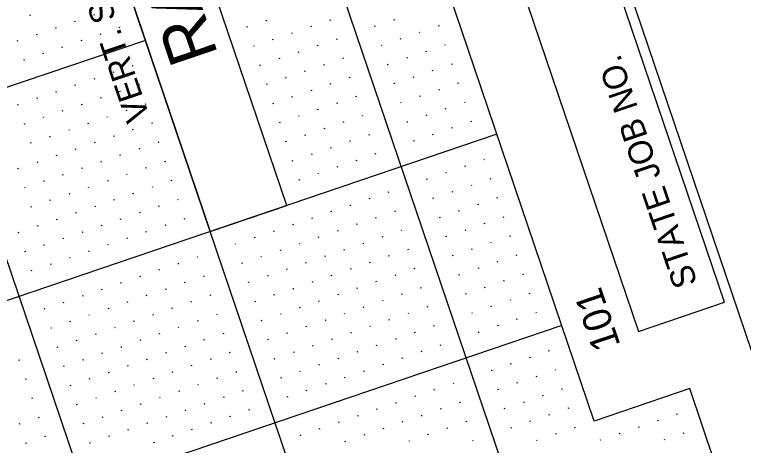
# Model space of a CAD drawing. Extents: x 2150318 to 2152065, y 143281 to 145371.
# Drawn here: x 2151290.7 to 2151471.2, y 145032.3 to 145139 of the extents above; entities that cross this region are included whole.
import ezdxf

# ---------------------------------------------------------------- set-up
doc = ezdxf.new("R2010")
doc.units = 0
for name, color, linetype in [('PR_Align_Ramp_J_Sta', 7, 'Continuous'), ('SHT_Plan_Profile_Sheet_Sta_Txt', 7, 'Continuous'), ('SHT_Plan_Profile_Sheet_Txt', 7, 'Continuous'), ('SHT_Profile_Grid_Major', 7, 'Continuous'), ('SHT_Profile_Grid_Minor', 7, 'Continuous'), ('SHT_Scale', 7, 'Continuous'), ('SHT_Sheet_Border', 7, 'Continuous')]:
    doc.layers.add(name, color=color, linetype=linetype)

msp = doc.modelspace()

# ---------------------------------------------------------------- linework, layer by layer
at = {"layer": 'SHT_Profile_Grid_Major'}
for p, q in [((2151832.26, 143787.41), (2151326.27, 145278.92)), ((2151784.91, 143771.34), (2151278.93, 145262.85)), ((2151737.57, 143755.28), (2151231.58, 145246.79)), ((2151323.1, 145132.64), (2150944.3, 145004.14)), ((2151410.19, 145109.39), (2150960.37, 144956.79)), ((2151426.25, 145062.04), (2150976.43, 144909.44))]:
    msp.add_line(p, q, dxfattribs=at)
at = {"layer": 'SHT_Profile_Grid_Minor'}
for p, q in [((2151294.65, 145138.7), (2151294.56, 145138.93)), ((2151305.72, 145137.17), (2151305.64, 145137.41)), ((2151310.46, 145138.78), (2151310.38, 145139.02)), ((2151353.15, 145137.43), (2151353.07, 145137.66)), ((2151368.97, 145137.51), (2151368.89, 145137.75)), ((2151384.78, 145137.59), (2151384.7, 145137.83)), ((2151300.99, 145135.57), (2151300.91, 145135.81)), ((2151316.8, 145135.65), (2151316.72, 145135.89)), ((2151348.42, 145135.82), (2151348.34, 145136.06)), ((2151364.23, 145135.9), (2151364.15, 145136.14)), ((2151380.04, 145135.99), (2151379.96, 145136.23)), ((2151395.85, 145136.07), (2151395.77, 145136.31)), ((2151296.25, 145133.96), (2151296.17, 145134.2)), ((2151312.06, 145134.05), (2151311.98, 145134.28)), ((2151359.5, 145134.3), (2151359.42, 145134.53)), ((2151391.12, 145134.47), (2151391.04, 145134.7)), ((2151291.52, 145132.36), (2151291.44, 145132.59)), ((2151307.33, 145132.44), (2151307.25, 145132.68)), ((2151354.76, 145132.69), (2151354.68, 145132.93)), ((2151370.57, 145132.78), (2151370.49, 145133.01)), ((2151386.38, 145132.86), (2151386.3, 145133.1)), ((2151302.59, 145130.83), (2151302.51, 145131.07)), ((2151350.03, 145131.09), (2151349.95, 145131.32)), ((2151365.84, 145131.17), (2151365.76, 145131.41)), ((2151381.65, 145131.25), (2151381.57, 145131.49)), ((2151397.46, 145131.34), (2151397.38, 145131.57)), ((2151297.86, 145129.23), (2151297.78, 145129.46)), ((2151361.1, 145129.56), (2151361.02, 145129.8)), ((2151392.72, 145129.73), (2151392.64, 145129.97)), ((2151293.12, 145127.62), (2151293.04, 145127.86)), ((2151351.63, 145126.35), (2151351.55, 145126.59)), ((2151356.37, 145127.96), (2151356.29, 145128.19)), ((2151367.44, 145126.43), (2151367.36, 145126.67)), ((2151372.18, 145128.04), (2151372.1, 145128.28)), ((2151383.25, 145126.52), (2151383.17, 145126.76)), ((2151387.99, 145128.12), (2151387.91, 145128.36)), ((2151399.07, 145126.6), (2151398.99, 145126.84)), ((2151315.28, 145124.58), (2151315.19, 145124.81)), ((2151320.01, 145126.18), (2151319.93, 145126.42)), ((2151362.71, 145124.83), (2151362.63, 145125.06)), ((2151394.33, 145125), (2151394.25, 145125.23)), ((2151310.54, 145122.97), (2151310.46, 145123.21)), ((2151357.97, 145123.22), (2151357.89, 145123.46)), ((2151373.78, 145123.31), (2151373.7, 145123.54)), ((2151389.6, 145123.39), (2151389.52, 145123.63)), ((2151305.81, 145121.36), (2151305.73, 145121.6)), ((2151321.62, 145121.45), (2151321.54, 145121.68)), ((2151353.24, 145121.62), (2151353.16, 145121.85)), ((2151369.05, 145121.7), (2151368.97, 145121.94)), ((2151384.86, 145121.78), (2151384.78, 145122.02)), ((2151400.67, 145121.87), (2151400.59, 145122.1)), ((2151301.07, 145119.76), (2151300.99, 145119.99)), ((2151316.88, 145119.84), (2151316.8, 145120.08)), ((2151364.32, 145120.09), (2151364.23, 145120.33)), ((2151395.94, 145120.26), (2151395.86, 145120.5)), ((2151296.34, 145118.15), (2151296.26, 145118.39)), ((2151312.15, 145118.23), (2151312.07, 145118.47)), ((2151359.58, 145118.49), (2151359.5, 145118.72)), ((2151375.39, 145118.57), (2151375.31, 145118.81)), ((2151391.2, 145118.65), (2151391.12, 145118.89)), ((2151291.6, 145116.54), (2151291.52, 145116.78)), ((2151307.41, 145116.63), (2151307.33, 145116.87)), ((2151323.22, 145116.71), (2151323.14, 145116.95)), ((2151354.85, 145116.88), (2151354.76, 145117.12)), ((2151370.66, 145116.96), (2151370.58, 145117.2)), ((2151386.47, 145117.05), (2151386.39, 145117.29)), ((2151397.54, 145115.53), (2151397.46, 145115.76)), ((2151402.28, 145117.13), (2151402.2, 145117.37)), ((2151302.68, 145115.02), (2151302.6, 145115.26)), ((2151318.49, 145115.11), (2151318.41, 145115.34)), ((2151361.19, 145113.75), (2151361.11, 145113.99)), ((2151365.92, 145115.36), (2151365.84, 145115.59)), ((2151377, 145113.84), (2151376.92, 145114.07)), ((2151392.81, 145113.92), (2151392.73, 145114.16)), ((2151297.94, 145113.42), (2151297.86, 145113.65)), ((2151309.02, 145111.89), (2151308.94, 145112.13)), ((2151313.75, 145113.5), (2151313.67, 145113.74)), ((2151324.83, 145111.98), (2151324.75, 145112.21)), ((2151356.45, 145112.15), (2151356.37, 145112.38)), ((2151372.26, 145112.23), (2151372.18, 145112.47)), ((2151388.07, 145112.31), (2151387.99, 145112.55)), ((2151403.89, 145112.4), (2151403.8, 145112.63)), ((2151293.21, 145111.81), (2151293.13, 145112.05)), ((2151304.28, 145110.29), (2151304.2, 145110.52)), ((2151320.09, 145110.37), (2151320.01, 145110.61)), ((2151367.53, 145110.62), (2151367.45, 145110.86)), ((2151399.15, 145110.79), (2151399.07, 145111.03)), ((2151299.55, 145108.68), (2151299.47, 145108.92)), ((2151315.36, 145108.76), (2151315.28, 145109)), ((2151362.79, 145109.02), (2151362.71, 145109.25)), ((2151378.6, 145109.1), (2151378.52, 145109.34)), ((2151394.42, 145109.18), (2151394.33, 145109.42)), ((2151294.81, 145107.07), (2151294.73, 145107.31)), ((2151310.62, 145107.16), (2151310.54, 145107.4)), ((2151326.44, 145107.24), (2151326.36, 145107.48)), ((2151358.06, 145107.41), (2151357.98, 145107.65)), ((2151373.87, 145107.49), (2151373.79, 145107.73)), ((2151389.68, 145107.58), (2151389.6, 145107.82)), ((2151305.89, 145105.55), (2151305.81, 145105.79)), ((2151321.7, 145105.64), (2151321.62, 145105.87)), ((2151369.13, 145105.89), (2151369.05, 145106.13)), ((2151301.15, 145103.95), (2151301.07, 145104.18)), ((2151316.97, 145104.03), (2151316.89, 145104.27)), ((2151364.4, 145104.28), (2151364.32, 145104.52)), ((2151380.21, 145104.37), (2151380.13, 145104.6)), ((2151407.1, 145102.93), (2151407.02, 145103.16)), ((2151296.42, 145102.34), (2151296.34, 145102.58)), ((2151312.23, 145102.42), (2151312.15, 145102.66)), ((2151328.04, 145102.51), (2151327.96, 145102.74)), ((2151359.66, 145102.68), (2151359.58, 145102.91)), ((2151370.74, 145101.15), (2151370.66, 145101.39)), ((2151375.48, 145102.76), (2151375.39, 145103)), ((2151402.36, 145101.32), (2151402.28, 145101.56)), ((2151291.68, 145100.73), (2151291.6, 145100.97)), ((2151307.5, 145100.82), (2151307.42, 145101.05)), ((2151318.57, 145099.3), (2151318.49, 145099.53)), ((2151323.31, 145100.9), (2151323.23, 145101.14)), ((2151366.01, 145099.55), (2151365.93, 145099.78)), ((2151397.63, 145099.72), (2151397.55, 145099.95)), ((2151298.03, 145097.6), (2151297.95, 145097.84)), ((2151302.76, 145099.21), (2151302.68, 145099.45)), ((2151313.84, 145097.69), (2151313.76, 145097.93)), ((2151329.65, 145097.77), (2151329.57, 145098.01)), ((2151361.27, 145097.94), (2151361.19, 145098.18)), ((2151392.89, 145098.11), (2151392.81, 145098.35)), ((2151408.7, 145098.19), (2151408.62, 145098.43)), ((2151293.29, 145096), (2151293.21, 145096.24)), ((2151309.1, 145096.08), (2151309.02, 145096.32)), ((2151324.91, 145096.17), (2151324.83, 145096.4)), ((2151403.97, 145096.59), (2151403.89, 145096.82)), ((2151304.37, 145094.48), (2151304.29, 145094.71)), ((2151320.18, 145094.56), (2151320.1, 145094.8)), ((2151383.42, 145094.9), (2151383.34, 145095.13)), ((2151399.23, 145094.98), (2151399.15, 145095.22)), ((2151299.63, 145092.87), (2151299.55, 145093.11)), ((2151315.44, 145092.95), (2151315.36, 145093.19)), ((2151331.25, 145093.04), (2151331.17, 145093.27)), ((2151378.69, 145093.29), (2151378.61, 145093.53)), ((2151394.5, 145093.37), (2151394.42, 145093.61)), ((2151410.31, 145093.46), (2151410.23, 145093.69)), ((2151294.9, 145091.26), (2151294.82, 145091.5)), ((2151310.71, 145091.35), (2151310.63, 145091.58)), ((2151326.52, 145091.43), (2151326.44, 145091.67)), ((2151373.95, 145091.68), (2151373.87, 145091.92)), ((2151400.84, 145090.25), (2151400.76, 145090.48)), ((2151405.58, 145091.85), (2151405.5, 145092.09)), ((2151305.97, 145089.74), (2151305.89, 145089.98)), ((2151321.78, 145089.83), (2151321.7, 145090.06)), ((2151364.48, 145088.47), (2151364.4, 145088.71)), ((2151369.22, 145090.08), (2151369.14, 145090.31)), ((2151380.29, 145088.55), (2151380.21, 145088.79)), ((2151385.03, 145090.16), (2151384.95, 145090.4)), ((2151396.11, 145088.64), (2151396.03, 145088.88)), ((2151411.92, 145088.72), (2151411.84, 145088.96)), ((2151301.24, 145088.13), (2151301.16, 145088.37)), ((2151317.05, 145088.22), (2151316.97, 145088.46)), ((2151328.13, 145086.7), (2151328.05, 145086.93)), ((2151332.86, 145088.3), (2151332.78, 145088.54)), ((2151359.75, 145086.86), (2151359.67, 145087.1)), ((2151375.56, 145086.95), (2151375.48, 145087.19)), ((2151407.18, 145087.12), (2151407.1, 145087.35)), ((2151291.77, 145084.92), (2151291.69, 145085.16)), ((2151296.5, 145086.53), (2151296.42, 145086.77)), ((2151307.58, 145085.01), (2151307.5, 145085.24)), ((2151312.31, 145086.61), (2151312.23, 145086.85)), ((2151323.39, 145085.09), (2151323.31, 145085.33)), ((2151355.01, 145085.26), (2151354.93, 145085.49)), ((2151370.82, 145085.34), (2151370.74, 145085.58)), ((2151386.64, 145085.43), (2151386.56, 145085.66)), ((2151402.45, 145085.51), (2151402.37, 145085.75)), ((2151302.84, 145083.4), (2151302.76, 145083.64)), ((2151318.66, 145083.48), (2151318.58, 145083.72)), ((2151350.28, 145083.65), (2151350.2, 145083.89)), ((2151366.09, 145083.74), (2151366.01, 145083.97)), ((2151381.9, 145083.82), (2151381.82, 145084.06)), ((2151397.71, 145083.9), (2151397.63, 145084.14)), ((2151413.52, 145083.99), (2151413.44, 145084.22)), ((2151298.11, 145081.79), (2151298.03, 145082.03)), ((2151313.92, 145081.88), (2151313.84, 145082.11)), ((2151345.54, 145082.05), (2151345.46, 145082.28)), ((2151361.35, 145082.13), (2151361.27, 145082.37)), ((2151377.17, 145082.21), (2151377.09, 145082.45)), ((2151408.79, 145082.38), (2151408.71, 145082.62)), ((2151293.37, 145080.19), (2151293.29, 145080.42)), ((2151309.19, 145080.27), (2151309.11, 145080.51)), ((2151356.62, 145080.52), (2151356.54, 145080.76)), ((2151372.43, 145080.61), (2151372.35, 145080.84)), ((2151388.24, 145080.69), (2151388.16, 145080.93)), ((2151404.05, 145080.78), (2151403.97, 145081.01)), ((2151304.45, 145078.66), (2151304.37, 145078.9)), ((2151336.07, 145078.83), (2151335.99, 145079.07)), ((2151351.88, 145078.92), (2151351.8, 145079.15)), ((2151367.7, 145079), (2151367.62, 145079.24)), ((2151383.51, 145079.08), (2151383.43, 145079.32)), ((2151399.32, 145079.17), (2151399.24, 145079.41)), ((2151410.39, 145077.65), (2151410.31, 145077.88)), ((2151415.13, 145079.25), (2151415.05, 145079.49)), ((2151299.72, 145077.06), (2151299.64, 145077.3)), ((2151331.34, 145077.23), (2151331.26, 145077.46)), ((2151347.15, 145077.31), (2151347.07, 145077.55)), ((2151358.23, 145075.79), (2151358.15, 145076.03)), ((2151362.96, 145077.39), (2151362.88, 145077.63)), ((2151374.04, 145075.87), (2151373.96, 145076.11)), ((2151378.77, 145077.48), (2151378.69, 145077.72)), ((2151389.85, 145075.96), (2151389.77, 145076.19)), ((2151405.66, 145076.04), (2151405.58, 145076.28)), ((2151294.98, 145075.45), (2151294.9, 145075.69)), ((2151321.87, 145074.01), (2151321.79, 145074.25)), ((2151326.6, 145075.62), (2151326.52, 145075.86)), ((2151337.68, 145074.1), (2151337.6, 145074.33)), ((2151353.49, 145074.18), (2151353.41, 145074.42)), ((2151369.3, 145074.27), (2151369.22, 145074.5)), ((2151385.11, 145074.35), (2151385.03, 145074.59)), ((2151400.92, 145074.43), (2151400.84, 145074.67)), ((2151416.74, 145074.52), (2151416.66, 145074.75)), ((2151317.13, 145072.41), (2151317.05, 145072.64)), ((2151332.94, 145072.49), (2151332.86, 145072.73)), ((2151348.76, 145072.58), (2151348.68, 145072.81)), ((2151364.57, 145072.66), (2151364.49, 145072.9)), ((2151380.38, 145072.74), (2151380.3, 145072.98)), ((2151412, 145072.91), (2151411.92, 145073.15)), ((2151312.4, 145070.8), (2151312.32, 145071.04)), ((2151328.21, 145070.89), (2151328.13, 145071.12)), ((2151359.83, 145071.05), (2151359.75, 145071.29)), ((2151375.64, 145071.14), (2151375.56, 145071.37)), ((2151391.45, 145071.22), (2151391.37, 145071.46)), ((2151407.27, 145071.31), (2151407.19, 145071.54)), ((2151307.66, 145069.2), (2151307.58, 145069.43)), ((2151323.47, 145069.28), (2151323.39, 145069.52)), ((2151339.29, 145069.36), (2151339.21, 145069.6)), ((2151355.1, 145069.45), (2151355.02, 145069.68)), ((2151370.91, 145069.53), (2151370.83, 145069.77)), ((2151386.72, 145069.62), (2151386.64, 145069.85)), ((2151402.53, 145069.7), (2151402.45, 145069.94)), ((2151418.34, 145069.78), (2151418.26, 145070.02)), ((2151302.93, 145067.59), (2151302.85, 145067.83)), ((2151318.74, 145067.67), (2151318.66, 145067.91)), ((2151334.55, 145067.76), (2151334.47, 145067.99)), ((2151350.36, 145067.84), (2151350.28, 145068.08)), ((2151366.17, 145067.92), (2151366.09, 145068.16)), ((2151381.98, 145068.01), (2151381.9, 145068.25)), ((2151413.61, 145068.18), (2151413.53, 145068.41)), ((2151298.19, 145065.98), (2151298.11, 145066.22)), ((2151314.01, 145066.07), (2151313.92, 145066.3)), ((2151329.82, 145066.15), (2151329.74, 145066.39)), ((2151361.44, 145066.32), (2151361.36, 145066.56)), ((2151377.25, 145066.4), (2151377.17, 145066.64)), ((2151393.06, 145066.49), (2151392.98, 145066.72)), ((2151404.14, 145064.96), (2151404.06, 145065.2)), ((2151408.87, 145066.57), (2151408.79, 145066.81)), ((2151419.95, 145065.05), (2151419.87, 145065.28)), ((2151309.27, 145064.46), (2151309.19, 145064.7)), ((2151325.08, 145064.54), (2151325, 145064.78)), ((2151340.89, 145064.63), (2151340.81, 145064.86)), ((2151356.7, 145064.71), (2151356.62, 145064.95)), ((2151367.78, 145063.19), (2151367.7, 145063.43)), ((2151372.51, 145064.8), (2151372.43, 145065.03)), ((2151383.59, 145063.27), (2151383.51, 145063.51)), ((2151388.33, 145064.88), (2151388.25, 145065.12)), ((2151415.21, 145063.44), (2151415.13, 145063.68)), ((2151304.54, 145062.85), (2151304.45, 145063.09)), ((2151320.35, 145062.94), (2151320.27, 145063.17)), ((2151331.42, 145061.42), (2151331.34, 145061.65)), ((2151336.16, 145063.02), (2151336.08, 145063.26)), ((2151351.97, 145063.11), (2151351.89, 145063.34)), ((2151363.04, 145061.58), (2151362.96, 145061.82)), ((2151378.86, 145061.67), (2151378.78, 145061.9)), ((2151394.67, 145061.75), (2151394.59, 145061.99)), ((2151410.48, 145061.84), (2151410.4, 145062.07)), ((2151299.8, 145061.25), (2151299.72, 145061.48)), ((2151310.88, 145059.73), (2151310.8, 145059.96)), ((2151315.61, 145061.33), (2151315.53, 145061.57)), ((2151326.69, 145059.81), (2151326.61, 145060.05)), ((2151342.5, 145059.89), (2151342.42, 145060.13)), ((2151358.31, 145059.98), (2151358.23, 145060.21)), ((2151374.12, 145060.06), (2151374.04, 145060.3)), ((2151389.93, 145060.15), (2151389.85, 145060.38)), ((2151405.74, 145060.23), (2151405.66, 145060.47)), ((2151306.14, 145058.12), (2151306.06, 145058.36)), ((2151321.95, 145058.2), (2151321.87, 145058.44)), ((2151337.76, 145058.29), (2151337.68, 145058.52)), ((2151353.57, 145058.37), (2151353.49, 145058.61)), ((2151369.39, 145058.45), (2151369.31, 145058.69)), ((2151385.2, 145058.54), (2151385.12, 145058.78)), ((2151301.41, 145056.51), (2151301.33, 145056.75)), ((2151317.22, 145056.6), (2151317.14, 145056.83)), ((2151333.03, 145056.68), (2151332.95, 145056.92)), ((2151364.65, 145056.85), (2151364.57, 145057.09)), ((2151380.46, 145056.93), (2151380.38, 145057.17)), ((2151396.27, 145057.02), (2151396.19, 145057.25)), ((2151312.48, 145054.99), (2151312.4, 145055.23)), ((2151328.29, 145055.07), (2151328.21, 145055.31)), ((2151344.1, 145055.16), (2151344.02, 145055.39)), ((2151359.92, 145055.24), (2151359.84, 145055.48)), ((2151375.73, 145055.33), (2151375.65, 145055.56)), ((2151391.54, 145055.41), (2151391.46, 145055.65)), ((2151423.16, 145055.58), (2151423.08, 145055.81)), ((2151291.94, 145053.3), (2151291.86, 145053.54)), ((2151307.75, 145053.38), (2151307.67, 145053.62)), ((2151323.56, 145053.47), (2151323.48, 145053.7)), ((2151339.37, 145053.55), (2151339.29, 145053.79)), ((2151355.18, 145053.64), (2151355.1, 145053.87)), ((2151370.99, 145053.72), (2151370.91, 145053.96)), ((2151386.8, 145053.8), (2151386.72, 145054.04)), ((2151413.69, 145052.37), (2151413.61, 145052.6)), ((2151418.43, 145053.97), (2151418.35, 145054.21)), ((2151303.01, 145051.78), (2151302.93, 145052.01)), ((2151318.82, 145051.86), (2151318.74, 145052.1)), ((2151334.64, 145051.95), (2151334.55, 145052.18)), ((2151361.52, 145050.51), (2151361.44, 145050.74)), ((2151366.26, 145052.11), (2151366.18, 145052.35)), ((2151377.33, 145050.59), (2151377.25, 145050.83)), ((2151382.07, 145052.2), (2151381.99, 145052.43)), ((2151408.96, 145050.76), (2151408.88, 145051)), ((2151424.77, 145050.84), (2151424.69, 145051.08)), ((2151314.09, 145050.26), (2151314.01, 145050.49)), ((2151325.17, 145048.73), (2151325.08, 145048.97)), ((2151329.9, 145050.34), (2151329.82, 145050.58)), ((2151340.98, 145048.82), (2151340.9, 145049.05)), ((2151345.71, 145050.42), (2151345.63, 145050.66)), ((2151356.79, 145048.9), (2151356.71, 145049.14)), ((2151372.6, 145048.98), (2151372.52, 145049.22)), ((2151420.03, 145049.24), (2151419.95, 145049.47)), ((2151293.54, 145048.56), (2151293.46, 145048.8)), ((2151304.62, 145047.04), (2151304.54, 145047.28)), ((2151309.35, 145048.65), (2151309.27, 145048.89)), ((2151320.43, 145047.13), (2151320.35, 145047.36)), ((2151336.24, 145047.21), (2151336.16, 145047.45)), ((2151367.86, 145047.38), (2151367.78, 145047.62)), ((2151399.49, 145047.55), (2151399.41, 145047.78)), ((2151415.3, 145047.63), (2151415.22, 145047.87)), ((2151315.7, 145045.52), (2151315.61, 145045.76)), ((2151331.51, 145045.6), (2151331.43, 145045.84)), ((2151347.32, 145045.69), (2151347.24, 145045.93)), ((2151363.13, 145045.77), (2151363.05, 145046.01)), ((2151394.75, 145045.94), (2151394.67, 145046.18)), ((2151410.56, 145046.02), (2151410.48, 145046.26)), ((2151426.37, 145046.11), (2151426.29, 145046.35)), ((2151295.15, 145043.83), (2151295.07, 145044.07)), ((2151310.96, 145043.91), (2151310.88, 145044.15)), ((2151326.77, 145044), (2151326.69, 145044.23)), ((2151342.58, 145044.08), (2151342.5, 145044.32)), ((2151358.39, 145044.17), (2151358.31, 145044.4)), ((2151390.02, 145044.33), (2151389.94, 145044.57)), ((2151421.64, 145044.5), (2151421.56, 145044.74)), ((2151306.23, 145042.31), (2151306.15, 145042.54)), ((2151322.04, 145042.39), (2151321.96, 145042.63)), ((2151337.85, 145042.48), (2151337.77, 145042.71)), ((2151385.28, 145042.73), (2151385.2, 145042.96)), ((2151401.09, 145042.81), (2151401.01, 145043.05)), ((2151416.9, 145042.9), (2151416.82, 145043.13)), ((2151317.3, 145040.79), (2151317.22, 145041.02)), ((2151333.11, 145040.87), (2151333.03, 145041.11)), ((2151348.92, 145040.95), (2151348.84, 145041.19)), ((2151380.55, 145041.12), (2151380.47, 145041.36)), ((2151396.36, 145041.21), (2151396.28, 145041.44)), ((2151412.17, 145041.29), (2151412.09, 145041.53)), ((2151423.24, 145039.77), (2151423.16, 145040)), ((2151427.98, 145041.37), (2151427.9, 145041.61)), ((2151454.87, 145039.94), (2151454.79, 145040.17)), ((2151296.76, 145039.1), (2151296.68, 145039.33)), ((2151312.57, 145039.18), (2151312.49, 145039.42)), ((2151328.38, 145039.26), (2151328.3, 145039.5)), ((2151344.19, 145039.35), (2151344.11, 145039.58)), ((2151371.08, 145037.91), (2151371, 145038.15)), ((2151375.81, 145039.51), (2151375.73, 145039.75)), ((2151386.89, 145037.99), (2151386.81, 145038.23)), ((2151391.62, 145039.6), (2151391.54, 145039.84)), ((2151402.7, 145038.08), (2151402.62, 145038.31)), ((2151418.51, 145038.16), (2151418.43, 145038.4)), ((2151450.13, 145038.33), (2151450.05, 145038.57)), ((2151292.02, 145037.49), (2151291.94, 145037.73)), ((2151307.83, 145037.57), (2151307.75, 145037.81)), ((2151323.64, 145037.66), (2151323.56, 145037.89)), ((2151334.72, 145036.13), (2151334.64, 145036.37)), ((2151339.45, 145037.74), (2151339.37, 145037.98)), ((2151366.34, 145036.3), (2151366.26, 145036.54)), ((2151382.15, 145036.39), (2151382.07, 145036.62)), ((2151397.96, 145036.47), (2151397.88, 145036.71)), ((2151413.77, 145036.55), (2151413.69, 145036.79)), ((2151429.59, 145036.64), (2151429.51, 145036.88)), ((2151445.4, 145036.72), (2151445.32, 145036.96)), ((2151298.36, 145034.36), (2151298.28, 145034.6)), ((2151314.17, 145034.44), (2151314.09, 145034.68)), ((2151318.91, 145036.05), (2151318.83, 145036.29)), ((2151329.98, 145034.53), (2151329.9, 145034.76)), ((2151361.61, 145034.7), (2151361.53, 145034.93)), ((2151377.42, 145034.78), (2151377.34, 145035.02)), ((2151393.23, 145034.86), (2151393.15, 145035.1)), ((2151424.85, 145035.03), (2151424.77, 145035.27)), ((2151440.66, 145035.12), (2151440.58, 145035.35)), ((2151456.47, 145035.2), (2151456.39, 145035.44)), ((2151293.63, 145032.75), (2151293.55, 145032.99)), ((2151309.44, 145032.84), (2151309.36, 145033.07)), ((2151325.25, 145032.92), (2151325.17, 145033.16)), ((2151372.68, 145033.17), (2151372.6, 145033.41)), ((2151388.49, 145033.26), (2151388.41, 145033.49)), ((2151404.3, 145033.34), (2151404.22, 145033.58)), ((2151420.12, 145033.43), (2151420.04, 145033.66)), ((2151435.93, 145033.51), (2151435.85, 145033.75)), ((2151451.74, 145033.59), (2151451.66, 145033.83))]:
    msp.add_line(p, q, dxfattribs=at)
at = {"layer": 'SHT_Sheet_Border'}
msp.add_line((2151879.61, 143803.47), (2151457.96, 145046.39), dxfattribs=at)
for points in [[(2150901.85, 143471.77), (2150395.86, 144963.28), (2151390.2, 145300.6), (2151896.19, 143809.09)], [(2151445.23, 145060.56), (2151466.54, 145067.79), (2151388.63, 145297.43), (2151367.32, 145290.2)], [(2151339.16, 145085.29), (2151358.1, 145091.72), (2151309.91, 145233.77), (2151290.97, 145227.34)]]:
    msp.add_lwpolyline(points, close=True, dxfattribs=at)
msp.add_lwpolyline([(2151457.96, 145046.39), (2151434.28, 145038.36), (2151362, 145251.44)], dxfattribs=at)

# ---------------------------------------------------------------- texts
at = {"layer": 'PR_Align_Ramp_J_Sta'}
msp.add_text('RAMP "J"', height=12, rotation=108.7393, dxfattribs=at).set_placement((2151341.18, 145129.15))
at = {"layer": 'SHT_Plan_Profile_Sheet_Sta_Txt'}
msp.add_text('101', height=7, rotation=108.7393, dxfattribs=at).set_placement((2151440.84, 145057.15))
at = {"layer": 'SHT_Plan_Profile_Sheet_Txt'}
msp.add_text('STATE JOB NO.', height=6, rotation=108.7393, dxfattribs=at).set_placement((2151459.92, 145072.52))
at = {"layer": 'SHT_Scale'}
msp.add_text('VERT. SCALE: 1" = 10\'', height=6, rotation=108.7393, dxfattribs=at).set_placement((2151324.27, 145113.62))

doc.saveas('drawing.dxf')
